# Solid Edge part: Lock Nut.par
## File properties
Author: Sarvanan
Template: sync iso part.par
Last saved by: Sarvanan
Revision: 3
Application: Solid Edge
Accuracy: 0.990
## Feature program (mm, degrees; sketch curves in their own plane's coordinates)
sketch for "Hole_1" plane through (21.0838, 43.6973, 8) normal (0, 0, 1) x-axis (1, 0, 0)
  hole centre (-1.3414, 0.2221) bore radius 6
hole "Hole_1" diameter 12 through
pattern "unnamed Pattern 1" of "Hole_1"
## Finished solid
Body 1: solid body, 21 faces, 56 edges, 36 vertices.
  Faces by surface: spun 12, plane 8, cylinder 1
  Edges by curve: circle 21, line 18, intersection 17
Bounding box of the edges (mm; curved faces can reach further): 30.022 x 26.000 x 8.000, from (4.7313, 30.9194, 0) to (34.7535, 56.9194, 8).
Cylindrical faces by radius (mm): R6 x1
Planar faces by outward normal: +y 1, +z 1, -y 1, -z 1, oblique 4
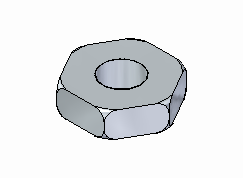
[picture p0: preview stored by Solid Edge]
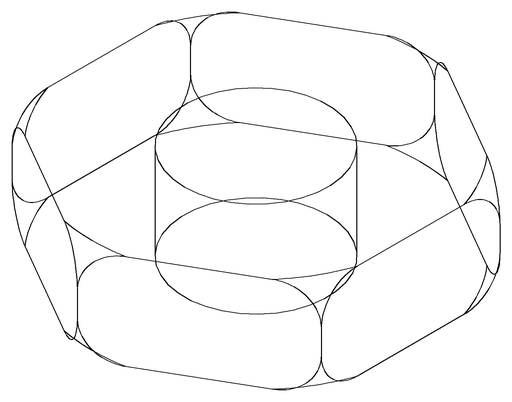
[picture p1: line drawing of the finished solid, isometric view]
